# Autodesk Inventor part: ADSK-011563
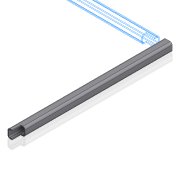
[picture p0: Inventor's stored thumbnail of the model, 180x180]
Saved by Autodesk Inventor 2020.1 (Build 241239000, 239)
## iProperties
Created: 2000-02
Part Number: ADSK-011563
Material: Pearson HRS
Document SubType Name: Modeling
Designer: sspink
Density: 7.83 g/cm^3
Appearance: Métal - Acier
Mass: 843.826 g
Surface Area: 724.772 cm^2
Volume: 107.768 cm^3
Control State: 0
Checked Out: False
Master: False
Shininess: 0.0
Length Units: 11269
Angle Units: 11279
Time Units: 11290
Mass Units: 11283
Length Display Precision: 3
Angle Display Precision: 2
Compacted: True
Dimensions: 25x460x25 mm
Mass: 0,844 kg
DocNumber: ADSK-011563.ipt
Folder: 01 - Themengebiete\Simplification\01 - Packaging machine\
VDS_Category: 3D Komponenten
VLT_Material: Pearson HRS
Density: 0.0
Volumn: 0.0
Area: 0.0
PropertySet Name: Model Information
Author: sspink
Revision Number: -
Title: profile
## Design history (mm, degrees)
node "TubeDesel1"
  sketch "Sketch2"
    geometry: L1 (31.4, 25.4)-(44.4, 25.4); L2 (50.4, 31.4)-(50.4, 44.4); L3 (44.4, 50.4)-(31.4, 50.4); L4 (25.4, 44.4)-(25.4, 31.4); L5 (47.4, 31.4)-(47.4, 44.4); L6 (44.4, 47.4)-(31.4, 47.4); L7 (28.4, 44.4)-(28.4, 31.4); L8 (31.4, 28.4)-(44.4, 28.4); A1 r 6 centre (31.4, 44.4) between (31.4, 50.4) and (25.4, 44.4); A2 r 6 centre (44.4, 44.4) between (50.4, 44.4) and (44.4, 50.4); A3 r 6 centre (44.4, 31.4) between (44.4, 25.4) and (50.4, 31.4); A4 r 6 centre (31.4, 31.4) between (25.4, 31.4) and (31.4, 25.4); A5 r 3 centre (44.4, 31.4) between (44.4, 28.4) and (47.4, 31.4); A6 r 3 centre (44.4, 44.4) between (47.4, 44.4) and (44.4, 47.4); A7 r 3 centre (31.4, 44.4) between (31.4, 47.4) and (28.4, 44.4); A8 r 3 centre (31.4, 31.4) between (28.4, 31.4) and (31.4, 28.4); 2 further points
    constraints: 16 end point, 16 point on circle, 16 tangent, 8 centre point, 4 parallel, 3 equal radius, 2 perpendicular, 2 point on line, 1 coincident, 1 horizontal, 7 other
    dimensions: "d0" = 25 distance between parallel lines of L3 L1 (derived); "d1" = 25 distance between parallel lines of L2 L4 (derived); "d2" = 6 radius of A1 (derived); "d3" = 3 distance between parallel lines of L2 L5 (derived)
node "Extrusion1" dims "d11" = 25, "d12" = 0
node "Extrusion2" dims "d18" = 25.4, "d19" = 0
node "Solide1"
node "Corps solides"
node "Corps surfaciques"
sketch "Sketch5"
  geometry: L1 (13, 3)-(0, 3) reference; L2 (0, 22)-(13, 22) reference; L3 (16, 19)-(16, 6) reference; L4 (13, 0)-(0, 0) reference; L5 (19, 19)-(19, 6) reference; L6 (0, 25)-(13, 25) reference; L7 (6.5, 25)-(6.5, 22); L8 (6.5, 3)-(6.5, 0); A1 r 3 centre (13, 19) between (16, 19) and (13, 22) reference; A2 r 3 centre (13, 6) between (13, 3) and (16, 6) reference; A3 r 6 centre (13, 6) between (13, 0) and (19, 6) reference; A4 r 6 centre (13, 19) between (19, 19) and (13, 25) reference
  constraints: 4 end point, 4 midpoint
sketch "Sketch7"
  geometry: L1 (13, 460)-(0, 460) reference; L2 (-0.644, 434.6)-(13.644, 434.6); L3 (13.644, 434.6)-(13.644, 396.5); L4 (13.644, 396.5)-(-0.644, 396.5); L5 (-0.644, 396.5)-(-0.644, 434.6); L6 (-0.644, 333)-(13.644, 333); L7 (13.644, 333)-(13.644, 294.9); L8 (13.644, 294.9)-(-0.644, 294.9); L9 (-0.644, 294.9)-(-0.644, 333); L10 (6.5, 460)-(6.5, 434.6); A1 r 7.144 centre (6.5, 434.6) between (13.644, 434.6) and (-0.644, 434.6); A2 r 7.144 centre (6.5, 396.5) between (-0.644, 396.5) and (13.644, 396.5); A3 r 7.144 centre (6.5, 333) between (13.644, 333) and (-0.644, 333); A4 r 7.144 centre (6.5, 294.9) between (-0.644, 294.9) and (13.644, 294.9)
  constraints: 18 end point, 8 point on circle, 5 parallel, 4 centre point, 4 tangent, 3 perpendicular, 2 horizontal, 2 midpoint, 1 vertical alignment
  dimensions: "d13" = 14.2875 distance of L2.start L2.end; "d14" = 38.1 distance of L2.end L3.end; "d15" = 25.4 distance between parallel lines of L2 L1; "d16" = 38.1 distance of L6.end L7.end; "d17" = 127 distance between parallel lines of L6 L1
